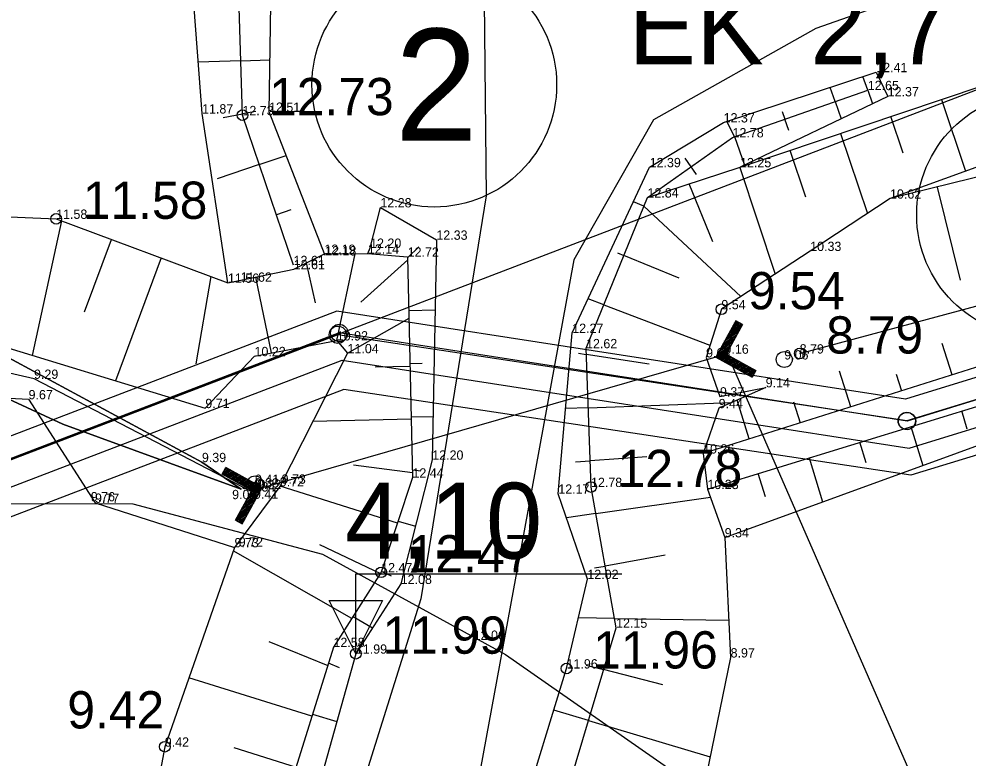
# Model space of a CAD drawing. Extents: x 433497 to 434382, y 6534486 to 6534993.
# Drawn here: x 433909 to 433944.68, y 6534891.36 to 6534919.14 of the extents above; entities that cross this region are included whole.
import ezdxf

# ---------------------------------------------------------------- set-up
doc = ezdxf.new("R2010")
doc.units = 0
for name, color, linetype in [('Default', 7, 'Continuous'), ('GEOLPUNKT', 7, 'Continuous'), ('jääkpaksus', 7, 'Continuous'), ('kataster', 7, 'Continuous'), ('KORGUS-EH2000', 7, 'Continuous'), ('Lamami horisontaal', 7, 'Continuous'), ('MOOTKORG-EH2000', 7, 'Continuous'), ('PIIR', 7, 'Continuous'), ('RELJEEF', 7, 'Continuous'), ('TEE', 7, 'Continuous'), ('TRUUP', 7, 'Continuous'), ('VEEKOGU', 7, 'Continuous')]:
    doc.layers.add(name, color=color, linetype=linetype)

msp = doc.modelspace()

# ---------------------------------------------------------------- linework, layer by layer
at = {"layer": 'Default'}
msp.add_lwpolyline([(433617.12, 6534791.025), (433632.75, 6534606.045), (434137.38, 6534796.515), (434127.69, 6534855.6), (433968.21, 6534911.925), (433942.38, 6534904.035), (433920.99, 6534907.275)], close=True, dxfattribs=at)
msp.add_lwpolyline([(433617.12, 6534791.025), (433632.75, 6534606.045), (434137.38, 6534796.515), (434127.69, 6534855.6), (433968.21, 6534911.925), (433942.38, 6534904.035), (433920.99, 6534907.275)], close=True, dxfattribs=at)
msp.add_lwpolyline([(433617.12, 6534791.025), (433632.75, 6534606.045), (434137.38, 6534796.515), (434127.69, 6534855.6), (433968.21, 6534911.925), (433942.38, 6534904.035), (433920.99, 6534907.275)], close=True, dxfattribs=at)
at = {"layer": 'jääkpaksus'}
msp.add_lwpolyline([(433921.669, 6534895.285), (433921.669, 6534898.285), (433931.669, 6534898.285)], dxfattribs=at)
msp.add_lwpolyline([(433921.669, 6534895.285), (433920.669, 6534897.285), (433922.669, 6534897.285)], close=True, dxfattribs=at)
at = {"layer": 'kataster'}
msp.add_lwpolyline([(433617.102, 6534791.002), (433632.769, 6534606.029), (434137.446, 6534796.469), (434127.827, 6534855.589), (433950.026, 6534918.39)], close=True, dxfattribs=at)
at = {"layer": 'KORGUS-EH2000'}
for centre in [(433917.405, 6534915.526), (433910.4, 6534911.63), (433935.41, 6534908.231), (433938.353, 6534906.567), (433930.509, 6534901.55), (433922.62, 6534898.344), (433921.669, 6534895.285), (433929.589, 6534894.729), (433914.485, 6534891.79)]:
    msp.add_circle(centre, 0.2, dxfattribs=at)
at = {"layer": 'Lamami horisontaal'}
msp.add_lwpolyline([(433901.435, 6534899.835), (433905.917, 6534900.93), (433913.287, 6534900.915), (433920.411, 6534899.023), (433927.288, 6534895.254), (433957.622, 6534874.107)], dxfattribs=at)
at = {"layer": 'PIIR'}
for points in [[(433632.021, 6534604.835), (434138.248, 6534795.936), (434128.468, 6534856.135), (433968.226, 6534912.818), (433942.33, 6534904.85), (433920.952, 6534908.165), (433616.327, 6534791.524), (433632.021, 6534604.835)], [(433632.732, 6534605.959), (434137.353, 6534796.454), (434127.754, 6534855.539), (433968.208, 6534911.976), (433942.39, 6534904.031), (433921.04, 6534907.341), (433617.174, 6534790.992), (433632.732, 6534605.959)]]:
    msp.add_lwpolyline(points, dxfattribs=at)
for points in [[(433618.234, 6534790.327), (433921.149, 6534906.313), (433942.464, 6534903.008), (433968.187, 6534910.923), (434126.862, 6534854.794), (434136.235, 6534797.101), (433633.617, 6534607.362)], [(433619.24, 6534789.695), (433634.52, 6534608.851), (434135.141, 6534797.808), (434125.908, 6534854.108), (433968.165, 6534909.82), (433942.53, 6534901.99), (433921.212, 6534905.219)], [(433619.24, 6534789.695), (433634.52, 6534608.851), (434135.141, 6534797.808), (434125.908, 6534854.108), (433968.165, 6534909.82), (433942.53, 6534901.99), (433921.212, 6534905.219)]]:
    msp.add_lwpolyline(points, close=True, dxfattribs=at)
for centre, radius in [((433924.616, 6534916.673), 4.6), ((433947.352, 6534911.782), 4.6), ((433920.99, 6534907.275), 0.325), ((433921.04, 6534907.341), 0.325), ((433942.38, 6534904.035), 0.325), ((433942.39, 6534904.031), 0.325)]:
    msp.add_circle(centre, radius, dxfattribs=at)
at = {"layer": 'RELJEEF'}
for p, q in [((433917.342, 6534917.572), (433918.436, 6534917.605)), ((433917.342, 6534917.572), (433915.741, 6534917.522)), ((433940.912, 6534916.467), (433940.733, 6534916.979)), ((433939.685, 6534916.039), (433939.499, 6534916.572)), ((433940.912, 6534916.467), (433941.09, 6534915.958)), ((433939.685, 6534916.039), (433939.911, 6534915.392)), ((433943.682, 6534916.112), (433944.587, 6534913.418)), ((433916.676, 6534915.443), (433917.404, 6534915.573)), ((433917.905, 6534915.662), (433917.404, 6534915.573)), ((433937.698, 6534915.663), (433937.797, 6534915.379)), ((433942.246, 6534914.105), (433941.786, 6534915.475)), ((433935.909, 6534914.72), (433935.617, 6534915.294)), ((433937.947, 6534914.95), (433937.797, 6534915.379)), ((433939.89, 6534914.838), (433940.9, 6534911.832)), ((433935.909, 6534914.72), (433936.282, 6534913.65)), ((433938.583, 6534912.449), (433937.994, 6534914.201)), ((433918.035, 6534913.677), (433916.448, 6534913.136)), ((433918.035, 6534913.677), (433919.043, 6534914.017)), ((433934.038, 6534913.91), (433934.465, 6534913.3)), ((433936.098, 6534913.564), (433937.427, 6534909.554)), ((433935.083, 6534910.77), (433934.197, 6534912.943)), ((433943.528, 6534912.827), (433944.391, 6534909.32)), ((433932.499, 6534912.104), (433932.103, 6534912.265)), ((433919.226, 6534911.97), (433918.681, 6534911.784)), ((433932.499, 6534912.104), (433936.143, 6534908.712)), ((433910.604, 6534911.554), (433909.492, 6534906.498)), ((433911.465, 6534908.133), (433912.479, 6534910.856)), ((433924.035, 6534910.582), (433923.616, 6534910.182)), ((433914.353, 6534910.159), (433912.635, 6534905.542)), ((433920.952, 6534907.058), (433921.643, 6534910.32)), ((433931.5, 6534910.351), (433931.743, 6534910.252)), ((433933.824, 6534909.404), (433931.743, 6534910.252)), ((433920.155, 6534908.474), (433919.811, 6534909.977)), ((433921.853, 6534908.494), (433923.617, 6534910.094)), ((433915.666, 6534906.182), (433916.227, 6534909.461)), ((433917.898, 6534909.441), (433918.487, 6534906.588)), ((433930.988, 6534908.4), (433930.401, 6534908.623)), ((433930.988, 6534908.4), (433934.981, 6534906.884)), ((433923.66, 6534908.182), (433924.646, 6534908.204)), ((433921.355, 6534906.578), (433923.666, 6534907.898)), ((433944.087, 6534905.766), (433943.713, 6534906.951)), ((433930.035, 6534906.576), (433930.33, 6534906.531)), ((433932.691, 6534906.171), (433930.33, 6534906.531)), ((433924.156, 6534906.193), (433923.704, 6534906.183)), ((433922.393, 6534906.066), (433923.706, 6534906.095)), ((433940.273, 6534904.561), (433939.847, 6534905.911)), ((433941.98, 6534905.797), (433942.18, 6534905.164)), ((433936.459, 6534903.356), (433935.997, 6534904.817)), ((433938.115, 6534904.752), (433938.366, 6534903.958)), ((433930.402, 6534904.532), (433929.556, 6534904.502)), ((433930.402, 6534904.532), (433935.79, 6534904.725)), ((433944.653, 6534903.729), (433944.445, 6534904.408)), ((433923.75, 6534904.095), (433920.051, 6534904.013)), ((433923.748, 6534904.183), (433924.57, 6534904.201)), ((433942.533, 6534903.821), (433942.98, 6534902.365)), ((433940.859, 6534902.457), (433940.621, 6534903.234)), ((433932.605, 6534902.686), (433930.474, 6534902.533)), ((433934.725, 6534902.808), (433934.725, 6534902.808)), ((433938.709, 6534902.647), (433939.216, 6534900.996)), ((433921.585, 6534902.39), (433923.794, 6534902.095)), ((433929.926, 6534902.494), (433930.474, 6534902.533)), ((433924.106, 6534902.144), (433923.792, 6534902.184)), ((433937.065, 6534901.186), (433936.797, 6534902.06)), ((433923.23, 6534900.187), (433918.817, 6534901.586)), ((433930.687, 6534900.55), (433934.995, 6534901.165)), ((433930.687, 6534900.55), (433929.587, 6534900.393)), ((433923.257, 6534900.271), (433923.904, 6534900.074)), ((433920.297, 6534899.394), (433922.588, 6534898.295)), ((433921.513, 6534896.609), (433917.06, 6534899.157)), ((433933.293, 6534898.983), (433931.038, 6534898.581)), ((433923.005, 6534898.194), (433922.629, 6534898.372)), ((433930.645, 6534898.511), (433931.038, 6534898.581)), ((433921.56, 6534896.683), (433922.295, 6534896.258)), ((433931.389, 6534896.612), (433930.032, 6534896.633)), ((433931.389, 6534896.612), (433935.687, 6534896.544)), ((433918.397, 6534895.744), (433920.611, 6534894.842)), ((433921.054, 6534894.753), (433920.637, 6534894.926)), ((433930.32, 6534894.854), (433930.983, 6534894.686)), ((433933.206, 6534894.121), (433930.983, 6534894.686)), ((433920.016, 6534892.932), (433915.389, 6534894.375)), ((433920.042, 6534893.016), (433920.954, 6534892.732)), ((433930.411, 6534892.769), (433929.107, 6534893.158)), ((433930.411, 6534892.769), (433934.988, 6534891.405)), ((433917.074, 6534891.754), (433919.42, 6534891.023))]:
    msp.add_line(p, q, dxfattribs=at)
for points in [[(434057.361, 6534943.115), (434035.636, 6534936.058), (434012.285, 6534930.403), (433995.831, 6534927.622), (433975.867, 6534921.841), (433966.352, 6534919.118), (433953.883, 6534915.376), (433941.75, 6534912.389)], [(433916.859, 6534909.226), (433915.886, 6534915.589), (433914.929, 6534928.35), (433915.083, 6534936.262), (433902.686, 6534937.354), (433889.273, 6534937.991), (433874.423, 6534938.173), (433860.653, 6534938.647), (433856.4, 6534938.377)], [(433920.515, 6534910.253), (433918.404, 6534915.652), (433918.602, 6534927.786), (433917.571, 6534937.244), (433916.197, 6534937.086)], [(433919.326, 6534909.891), (433917.405, 6534915.526), (433917.007, 6534928.464), (433916.866, 6534936.048)], [(434013.638, 6534923.923), (434011.282, 6534922.743), (434005.856, 6534921.218), (434002.425, 6534920.296), (433994.862, 6534918.741), (433980.849, 6534915.581), (433976.065, 6534914.227), (433972.133, 6534912.733), (433966.809, 6534911.293), (433961.061, 6534910.056), (433948.062, 6534907.022), (433934.725, 6534902.808)], [(433934.885, 6534901.473), (433948.355, 6534905.609), (433960.823, 6534908.761), (433967.491, 6534910.261), (433971.618, 6534909.694), (433975.796, 6534909.256), (433984.352, 6534910.069), (433996.051, 6534908.124), (433997.709, 6534908.113), (433998.331, 6534911.388), (434003.22, 6534915.751), (434010.674, 6534918.326)], [(433935.534, 6534899.657), (433948.664, 6534904.432), (433960.648, 6534906.657), (433966.716, 6534907.784), (433971.868, 6534905.042), (433980.359, 6534904.292), (433982.759, 6534904.361), (433990.414, 6534903.325), (433999.356, 6534904.364), (434001.493, 6534910.875), (434009.433, 6534914.722), (434013.438, 6534918.41)], [(433896.085, 6534836.246), (433907.73, 6534849.047), (433914.836, 6534857.237), (433920.085, 6534863.955), (433925.913, 6534875.128), (433927.486, 6534882.954), (433931.452, 6534896.261), (433930.509, 6534901.55), (433930.322, 6534906.766), (433932.632, 6534912.431), (433936.113, 6534913.569), (433948.309, 6534917.667)], [(433895.887, 6534836.671), (433906.99, 6534849.543), (433914.294, 6534857.948), (433919.223, 6534864.624), (433924.866, 6534875.211), (433926.408, 6534881.232), (433926.099, 6534883.348), (433929.589, 6534894.729), (433930.371, 6534898.093), (433929.278, 6534901.297), (433929.803, 6534907.342), (433932.713, 6534913.57), (433935.494, 6534915.253), (433941.232, 6534917.143)], [(433941.232, 6534917.143), (433941.662, 6534916.233), (433936.113, 6534913.569)], [(433953.287, 6534916.572), (433941.75, 6534912.389), (433938.749, 6534910.421), (433935.41, 6534908.231), (433934.834, 6534906.421), (433935.357, 6534904.952), (433937.075, 6534905.296), (433935.31, 6534904.512), (433934.725, 6534902.808), (433934.885, 6534901.473), (433935.534, 6534899.657), (433935.756, 6534895.142), (433934.753, 6534890.261), (433935.088, 6534889.742), (433930.79, 6534874.949), (433925.594, 6534862.047), (433917.937, 6534854.555), (433909.717, 6534846.854), (433896.607, 6534835.953)], [(433932.632, 6534912.431), (433935.829, 6534914.692), (433940.912, 6534916.467)], [(433763.585, 6534891.607), (433768.482, 6534879.707), (433779.317, 6534877.624), (433783.641, 6534876.671), (433789.159, 6534878.039), (433798.484, 6534881.14), (433803.042, 6534877.671), (433810.627, 6534877.969), (433823.017, 6534882.312), (433834.298, 6534889.425), (433849.2, 6534895.864), (433854.211, 6534899.146), (433866.477, 6534901.86), (433879.364, 6534904.946), (433889.384, 6534907.925), (433901.971, 6534911.994), (433910.4, 6534911.63), (433916.859, 6534909.226), (433919.332, 6534909.737), (433920.484, 6534910.314), (433922.121, 6534910.322), (433923.615, 6534910.205)], [(433922.121, 6534910.322), (433922.204, 6534910.54), (433922.59, 6534912.061), (433924.695, 6534910.843), (433924.54, 6534902.576), (433923.354, 6534897.907), (433921.669, 6534895.285), (433918.585, 6534884.278), (433913.05, 6534871.656), (433903.969, 6534859.265), (433894.305, 6534845.672), (433892.501, 6534844.802)], [(433923.615, 6534910.205), (433923.798, 6534901.905), (433922.62, 6534898.344), (433920.827, 6534895.534), (433917.246, 6534884.05), (433911.896, 6534872.374), (433902.608, 6534859.27), (433894.514, 6534847), (433892.501, 6534844.802)], [(433907.052, 6534907.24), (433916.008, 6534904.516), (433917.858, 6534906.468), (433920.952, 6534907.058), (433921.355, 6534906.578), (433918.811, 6534901.575), (433917.104, 6534899.283), (433914.485, 6534891.79), (433912.65, 6534882.047), (433911.296, 6534879.715), (433907.843, 6534872.13), (433899.687, 6534858.873), (433894.244, 6534849.654), (433892.501, 6534844.802)]]:
    msp.add_lwpolyline(points, dxfattribs=at)
at = {"layer": 'TEE'}
for points in [[(433861.438, 6534942.159), (433869.211, 6534941.983), (433884.56, 6534941.789), (433912.385, 6534941.438), (433914.504, 6534939.939), (433923.131, 6534931.509), (433926.468, 6534922.294), (433926.566, 6534912.494), (433924.107, 6534897.344), (433917.239, 6534875.453), (433907.496, 6534860.59), (433898.243, 6534848.994), (433898.296, 6534849.051), (433891.969, 6534842.99)], [(433946.971, 6534921.598), (433938.961, 6534918.789), (433932.862, 6534915.346), (433929.862, 6534910.084), (433927.993, 6534899.902), (433926.253, 6534890.427), (433921.703, 6534874.038), (433912.286, 6534858.358), (433907.932, 6534852.587), (433902.598, 6534846.653), (433894.713, 6534836.682), (433880.242, 6534822.442), (433871.952, 6534814.761), (433862.656, 6534809.713), (433848.041, 6534804.286)]]:
    msp.add_lwpolyline(points, dxfattribs=at)
at = {"layer": 'TRUUP'}
for p, q in [((433935.952, 6534907.799), (433935.199, 6534906.436)), ((433936.076, 6534907.73), (433935.392, 6534906.492)), ((433936.201, 6534907.661), (433935.585, 6534906.548)), ((433936.199, 6534907.662), (433935.68, 6534907.308)), ((433936.15, 6534907.689), (433935.734, 6534907.405)), ((433936.101, 6534907.716), (433935.788, 6534907.502)), ((433936.052, 6534907.743), (433935.841, 6534907.599)), ((433936.003, 6534907.77), (433935.895, 6534907.697)), ((433936.201, 6534907.661), (433935.952, 6534907.799)), ((433935.988, 6534907.275), (433935.465, 6534906.919)), ((433936.042, 6534907.373), (433935.519, 6534907.016)), ((433936.095, 6534907.47), (433935.573, 6534907.113)), ((433936.149, 6534907.567), (433935.626, 6534907.21)), ((433935.773, 6534906.886), (433935.25, 6534906.53)), ((433935.826, 6534906.984), (433935.304, 6534906.627)), ((433935.88, 6534907.081), (433935.358, 6534906.724)), ((433935.934, 6534907.178), (433935.411, 6534906.821)), ((433935.719, 6534906.789), (433935.2, 6534906.435)), ((433935.665, 6534906.692), (433935.249, 6534906.408)), ((433935.611, 6534906.595), (433935.298, 6534906.381)), ((433935.611, 6534906.534), (433935.347, 6534906.354)), ((433935.585, 6534906.548), (433936.699, 6534905.932)), ((433917.954, 6534901.471), (433935.392, 6534906.492)), ((433935.199, 6534906.436), (433936.561, 6534905.683)), ((433935.392, 6534906.492), (433936.63, 6534905.808)), ((433935.66, 6534906.507), (433935.396, 6534906.327)), ((433935.709, 6534906.48), (433935.445, 6534906.3)), ((433935.758, 6534906.452), (433935.494, 6534906.273)), ((433935.807, 6534906.425), (433935.543, 6534906.246)), ((433935.856, 6534906.398), (433935.592, 6534906.218)), ((433935.905, 6534906.371), (433935.641, 6534906.191)), ((433935.954, 6534906.344), (433935.69, 6534906.164)), ((433936.003, 6534906.317), (433935.739, 6534906.137)), ((433936.052, 6534906.29), (433935.788, 6534906.11)), ((433936.101, 6534906.263), (433935.837, 6534906.083)), ((433936.15, 6534906.236), (433935.886, 6534906.056)), ((433936.199, 6534906.209), (433935.935, 6534906.029)), ((433936.248, 6534906.182), (433935.984, 6534906.002)), ((433936.297, 6534906.154), (433936.033, 6534905.975)), ((433936.346, 6534906.127), (433936.082, 6534905.948)), ((433936.395, 6534906.1), (433936.131, 6534905.92)), ((433936.444, 6534906.073), (433936.18, 6534905.893)), ((433936.493, 6534906.046), (433936.229, 6534905.866)), ((433936.542, 6534906.019), (433936.278, 6534905.839)), ((433936.591, 6534905.992), (433936.327, 6534905.812)), ((433936.64, 6534905.965), (433936.376, 6534905.785)), ((433936.689, 6534905.938), (433936.425, 6534905.758)), ((433936.655, 6534905.854), (433936.474, 6534905.731)), ((433936.699, 6534905.932), (433936.561, 6534905.683)), ((433936.602, 6534905.757), (433936.523, 6534905.704)), ((433916.647, 6534902.031), (433916.785, 6534902.28)), ((433916.744, 6534902.206), (433916.823, 6534902.259)), ((433918.147, 6534901.527), (433916.785, 6534902.28)), ((433917.761, 6534901.415), (433916.647, 6534902.031)), ((433916.657, 6534902.025), (433916.921, 6534902.205)), ((433916.691, 6534902.109), (433916.872, 6534902.232)), ((433916.706, 6534901.998), (433916.97, 6534902.178)), ((433917.954, 6534901.471), (433916.716, 6534902.155)), ((433916.755, 6534901.971), (433917.019, 6534902.151)), ((433916.804, 6534901.944), (433917.068, 6534902.124)), ((433916.853, 6534901.917), (433917.117, 6534902.097)), ((433916.902, 6534901.89), (433917.166, 6534902.07)), ((433916.951, 6534901.863), (433917.215, 6534902.043)), ((433917, 6534901.836), (433917.264, 6534902.015)), ((433917.049, 6534901.809), (433917.313, 6534901.988)), ((433917.098, 6534901.781), (433917.362, 6534901.961)), ((433917.147, 6534901.754), (433917.411, 6534901.934)), ((433917.196, 6534901.727), (433917.46, 6534901.907)), ((433917.245, 6534901.7), (433917.509, 6534901.88)), ((433917.294, 6534901.673), (433917.558, 6534901.853)), ((433917.343, 6534901.646), (433917.607, 6534901.826)), ((433917.392, 6534901.619), (433917.656, 6534901.799)), ((433917.441, 6534901.592), (433917.705, 6534901.772)), ((433917.49, 6534901.565), (433917.754, 6534901.745)), ((433917.539, 6534901.538), (433917.803, 6534901.717)), ((433917.588, 6534901.511), (433917.852, 6534901.69)), ((433917.637, 6534901.483), (433917.901, 6534901.663)), ((433917.681, 6534901.271), (433918.097, 6534901.555)), ((433917.686, 6534901.456), (433917.95, 6534901.636)), ((433917.735, 6534901.429), (433917.999, 6534901.609)), ((433917.735, 6534901.368), (433918.048, 6534901.582)), ((433917.145, 6534900.302), (433917.761, 6534901.415)), ((433917.27, 6534900.233), (433917.954, 6534901.471)), ((433917.394, 6534900.164), (433918.147, 6534901.527)), ((433917.466, 6534900.882), (433917.988, 6534901.239)), ((433917.52, 6534900.979), (433918.042, 6534901.336)), ((433917.573, 6534901.077), (433918.096, 6534901.433)), ((433917.627, 6534901.174), (433918.146, 6534901.528)), ((433917.251, 6534900.493), (433917.773, 6534900.85)), ((433917.304, 6534900.59), (433917.827, 6534900.947)), ((433917.358, 6534900.688), (433917.881, 6534901.044)), ((433917.412, 6534900.785), (433917.935, 6534901.142)), ((433917.147, 6534900.301), (433917.666, 6534900.655)), ((433917.196, 6534900.274), (433917.612, 6534900.558)), ((433917.197, 6534900.396), (433917.72, 6534900.753)), ((433917.145, 6534900.302), (433917.394, 6534900.164)), ((433917.245, 6534900.247), (433917.558, 6534900.461)), ((433917.294, 6534900.22), (433917.505, 6534900.364)), ((433917.343, 6534900.193), (433917.451, 6534900.266))]:
    msp.add_line(p, q, dxfattribs=at)
msp.add_lwpolyline([(433952.849, 6534888.951), (433943.324, 6534888.951), (433935.611, 6534906.595)], dxfattribs=at)
at = {"layer": 'VEEKOGU'}
for points in [[(433938.353, 6534906.567), (434032.024, 6534931.768), (434057.768, 6534939.003)], [(433762.728, 6534893.927), (433766.059, 6534880.045), (433768.451, 6534877.273), (433777.011, 6534876.737), (433783.737, 6534875.048), (433789.533, 6534875.633), (433792.948, 6534877.948), (433797.961, 6534878.694), (433803.158, 6534876.065), (433815.183, 6534876.407), (433824.703, 6534879.159), (433850.58, 6534889.135), (433868.878, 6534896.391), (433880.761, 6534900.001), (433893.386, 6534905.095), (433900.632, 6534907.256), (433907.052, 6534907.24), (433915.879, 6534902.485), (433917.357, 6534901.473)], [(433917.357, 6534901.473), (433915.879, 6534902.485), (433907.052, 6534907.24), (433900.632, 6534907.256), (433893.386, 6534905.095), (433880.761, 6534900.001), (433868.878, 6534896.391), (433850.58, 6534889.135), (433824.703, 6534879.159), (433815.183, 6534876.407), (433803.158, 6534876.065), (433797.961, 6534878.694), (433792.948, 6534877.948), (433789.533, 6534875.633), (433783.737, 6534875.048), (433777.011, 6534876.737), (433768.451, 6534877.273), (433766.059, 6534880.045), (433762.728, 6534893.927)], [(433917.357, 6534901.473), (433910.646, 6534903.91), (433905.733, 6534906.185), (433897.201, 6534904.664), (433864.652, 6534892.255), (433840.997, 6534882.39), (433822.758, 6534877.106), (433813.338, 6534872.69), (433806.812, 6534870.137), (433792.733, 6534866.126), (433778.163, 6534862.151), (433760.314, 6534861.045), (433757.652, 6534861.824), (433749.479, 6534854.726), (433748.765, 6534853.283)], [(433749.479, 6534854.726), (433757.652, 6534861.824), (433760.314, 6534861.045), (433778.163, 6534862.151), (433792.733, 6534866.126), (433806.812, 6534870.137), (433813.338, 6534872.69), (433822.758, 6534877.106), (433840.997, 6534882.39), (433864.652, 6534892.255), (433897.201, 6534904.664), (433905.733, 6534906.185), (433910.646, 6534903.91), (433917.357, 6534901.473)], [(433917.729, 6534901.381), (433909.569, 6534905.615), (433905.783, 6534906.485), (433897.022, 6534905.145), (433882.849, 6534899.96), (433864.095, 6534893.13), (433840.653, 6534883.7), (433822.307, 6534877.511)], [(433906.831, 6534905.005), (433907.409, 6534904.959), (433909.363, 6534904.847), (433911.861, 6534900.956), (433917.104, 6534899.283)]]:
    msp.add_lwpolyline(points, dxfattribs=at)
for centre in [(433937.773, 6534906.343), (433917.876, 6534901.668)]:
    msp.add_circle(centre, 0.3, dxfattribs=at)

# ---------------------------------------------------------------- texts
at = {"layer": 'GEOLPUNKT'}
for s, p in [('EK', (433931.918, 6534917.439)), ('2,7', (433938.749, 6534917.437))]:
    msp.add_text(s, height=2.85, dxfattribs=at).set_placement(p)
at = {"layer": 'jääkpaksus'}
msp.add_text('4,10', height=2.85, rotation=360, dxfattribs=at).set_placement((433921.257, 6534898.86))
at = {"layer": 'KORGUS-EH2000'}
for s, p in [('12.73', (433918.405, 6534915.526)), ('11.58', (433911.4, 6534911.63)), ('9.54', (433936.41, 6534908.231)), ('8.79', (433939.353, 6534906.567)), ('12.78', (433931.509, 6534901.55)), ('12.47', (433923.62, 6534898.344)), ('11.99', (433922.669, 6534895.285)), ('11.96', (433930.589, 6534894.729)), ('9.42', (433910.819, 6534892.477))]:
    msp.add_text(s, height=1.4, dxfattribs=at).set_placement(p)
at = {"layer": 'MOOTKORG-EH2000'}
for s, p in [('12.41', (433941.232, 6534917.143)), ('12.65', (433940.912, 6534916.467)), ('12.37', (433941.662, 6534916.233)), ('11.87', (433915.886, 6534915.589)), ('12.73', (433917.405, 6534915.526)), ('12.51', (433918.404, 6534915.652)), ('12.37', (433935.494, 6534915.253)), ('12.78', (433935.829, 6534914.692)), ('12.39', (433932.713, 6534913.57)), ('12.25', (433936.113, 6534913.569)), ('12.84', (433932.632, 6534912.431)), ('10.62', (433941.75, 6534912.389)), ('12.28', (433922.59, 6534912.061)), ('11.58', (433910.4, 6534911.63)), ('12.33', (433924.695, 6534910.843)), ('12.20', (433922.204, 6534910.54)), ('12.19', (433920.484, 6534910.314)), ('12.18', (433920.515, 6534910.253)), ('12.14', (433922.121, 6534910.322)), ('12.72', (433923.615, 6534910.205)), ('10.33', (433938.749, 6534910.421)), ('12.61', (433919.326, 6534909.891)), ('12.61', (433919.332, 6534909.737)), ('11.56', (433916.859, 6534909.226)), ('11.62', (433917.336, 6534909.265)), ('9.54', (433935.41, 6534908.231)), ('12.27', (433929.803, 6534907.342)), ('10.92', (433920.952, 6534907.058)), ('11.04', (433921.355, 6534906.578)), ('12.62', (433930.322, 6534906.766)), ('9.16', (433935.527, 6534906.559)), ('8.79', (433938.353, 6534906.567)), ('10.22', (433917.858, 6534906.468)), ('9.63', (433934.834, 6534906.421)), ('9.06', (433937.773, 6534906.343)), ('9.29', (433909.569, 6534905.615)), ('9.14', (433937.075, 6534905.296)), ('9.67', (433909.363, 6534904.847)), ('9.37', (433935.357, 6534904.952)), ('9.71', (433916.008, 6534904.516)), ('9.44', (433935.31, 6534904.512)), ('10.26', (433934.725, 6534902.808)), ('9.39', (433915.879, 6534902.485)), ('12.20', (433924.54, 6534902.576)), ('12.44', (433923.798, 6534901.905)), ('9.41', (433917.876, 6534901.668)), ('9.72', (433918.811, 6534901.575)), ('9.73', (433918.874, 6534901.674)), ('12.78', (433930.509, 6534901.55)), ('9.40', (433917.357, 6534901.473)), ('9.34', (433917.729, 6534901.381)), ('9.33', (433917.863, 6534901.53)), ('9.32', (433917.954, 6534901.471)), ('12.17', (433929.278, 6534901.297)), ('10.23', (433934.885, 6534901.473)), ('9.76', (433911.702, 6534901.013)), ('9.77', (433911.861, 6534900.956)), ('9.08', (433917.016, 6534901.094)), ('9.41', (433917.839, 6534901.108)), ('9.34', (433935.534, 6534899.657)), ('9.73', (433917.104, 6534899.283)), ('9.72', (433917.266, 6534899.314)), ('12.47', (433922.62, 6534898.344)), ('12.02', (433930.371, 6534898.093)), ('12.08', (433923.354, 6534897.907)), ('12.15', (433931.452, 6534896.261)), ('12.58', (433920.827, 6534895.534)), ('12.06', (433926.098, 6534895.806)), ('11.99', (433921.669, 6534895.285)), ('8.97', (433935.756, 6534895.142)), ('11.96', (433929.589, 6534894.729)), ('9.42', (433914.485, 6534891.79))]:
    msp.add_text(s, height=0.35, dxfattribs=at).set_placement(p)
at = {"layer": 'PIIR'}
msp.add_text('2', height=4.2, dxfattribs=at).set_placement((433923.132, 6534914.573))

doc.saveas('drawing.dxf')
